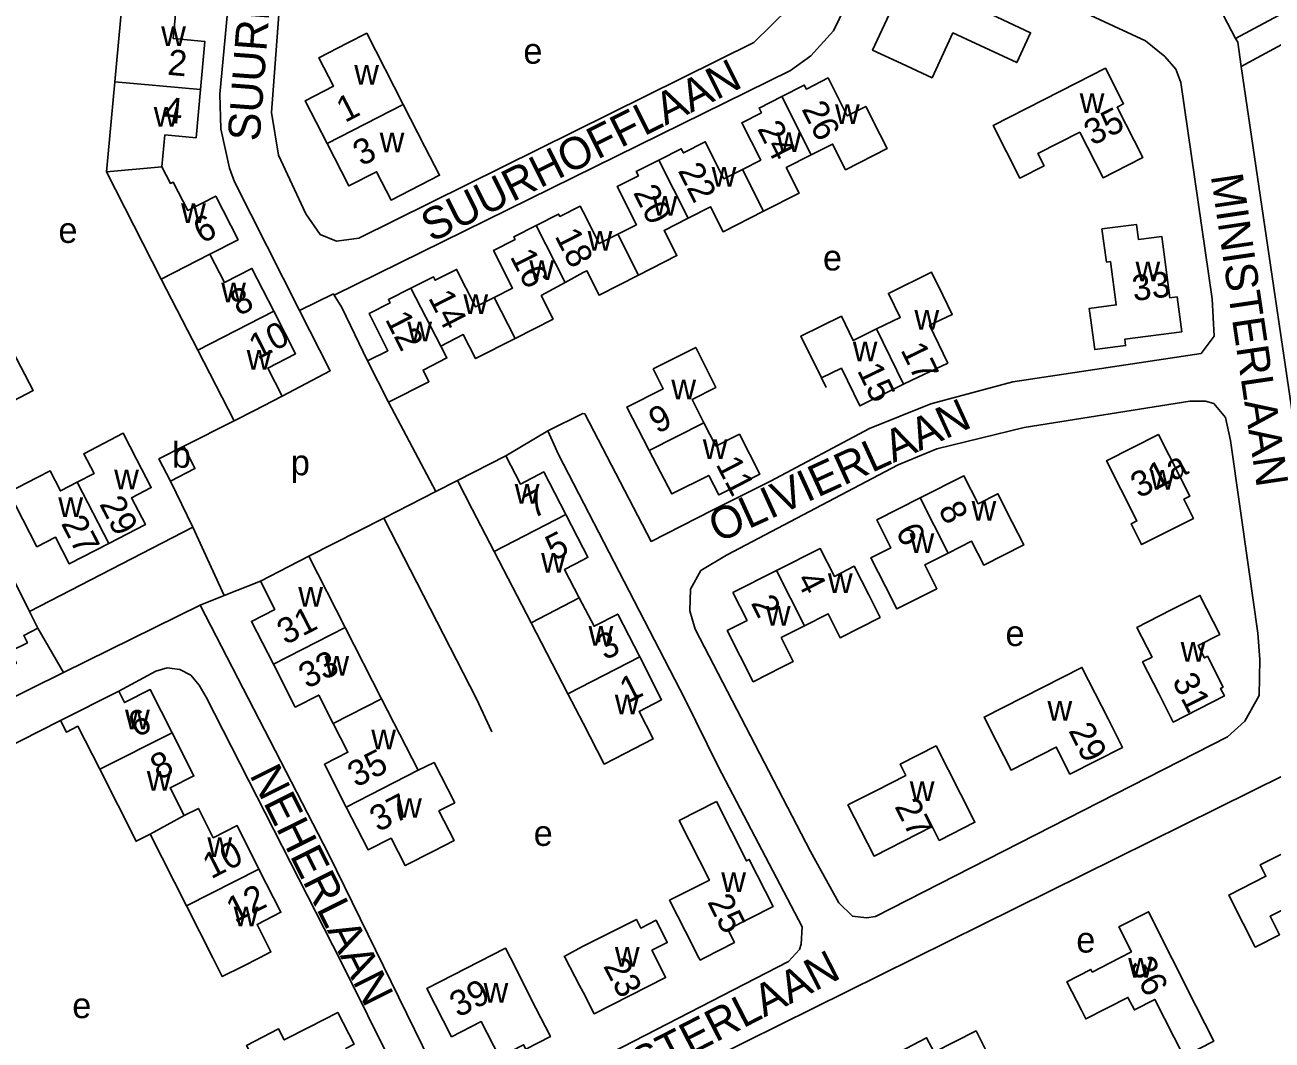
# Model space of a CAD drawing. Extents: x 162427 to 165104, y 384242 to 386287.
# Drawn here: x 163912.8 to 164107.7, y 384987.1 to 385145.8 of the extents above; entities that cross this region are included whole.
import ezdxf

# ---------------------------------------------------------------- set-up
doc = ezdxf.new("R2010")
doc.units = 0
for name, color, linetype in [('BLT_Basislijn', 7, 'Continuous'), ('BLT_Bebouwing', 7, 'Continuous'), ('BLT_Centroide', 7, 'Continuous'), ('BLT_Huisnummer', 7, 'Continuous'), ('BLT_Huisnummer_ tussenligend', 7, 'Continuous'), ('BLT_Onderverdeling_panden', 7, 'Continuous'), ('BLT_Straatnaam', 7, 'Continuous')]:
    doc.layers.add(name, color=color, linetype=linetype)

msp = doc.modelspace()

# ---------------------------------------------------------------- linework, layer by layer
at = {"layer": 'BLT_Basislijn'}
for p, q in [((164100.08, 385147.29), (164101.95, 385143.68)), ((163976.99, 385072.86), (163969.59, 385086.84)), ((163987.89, 385078.48), (163994.5, 385082.38)), ((163976.99, 385072.86), (163980.35, 385074.58)), ((163968.85, 385068.73), (163976.99, 385072.86)), ((163957.11, 385062.75), (163968.85, 385068.73)), ((163939, 385067.3), (163943.91, 385056.61)), ((163943.91, 385056.61), (163949.56, 385058.89)), ((163940.13, 385055.09), (163918.79, 385044.59)), ((163940.13, 385055.09), (163943.91, 385056.61)), ((163918.79, 385044.59), (163914.79, 385051.52)), ((163870.49, 385020.87), (163918.79, 385044.59)), ((163941.1, 385040.74), (163962.18, 384999.38)), ((163962.18, 384999.38), (163973.24, 384977.11))]:
    msp.add_line(p, q, dxfattribs=at)
for points in [[(163888.92, 385099.03), (163892.17, 385100.78), (163883.54, 385118.73), (163882.35, 385122.09), (163882.92, 385132.31), (163886.87, 385181.05), (163887.24, 385182.8), (163888.99, 385185.31), (163890.71, 385185.84), (163892.89, 385185.88), (163936.03, 385182.55), (163944.89, 385181.59), (163946.8, 385179.9), (163947.05, 385176.26), (163943.23, 385134.98), (163943.39, 385129.54), (163944.73, 385123.43), (163945.53, 385121.28), (163955.66, 385101.15)], [(164028.62, 385170.3), (164036.3, 385167.05), (164039, 385164.73), (164039.21, 385162.28), (164034.17, 385151.84), (164032.22, 385148.46), (164026.69, 385143.03), (163964.96, 385112.45), (163961.43, 385111.99), (163958.89, 385113.06), (163956.66, 385116.27), (163952.37, 385125.43), (163951.27, 385132.11), (163954.57, 385176.02), (163955.8, 385178.75), (163958.6, 385180.24), (164005.85, 385176.18), (164014.12, 385174.75), (164025.4, 385171.51), (164028.62, 385170.3)], [(164101.95, 385143.68), (164139.93, 385164.03), (164144.2, 385165.75), (164147.78, 385165.76), (164157.35, 385163.13)], [(163961.08, 385103.59), (164032.42, 385138.66), (164035.6, 385140.95), (164039.13, 385144.88), (164045.75, 385158.55), (164047.12, 385160.3), (164047.83, 385160.67), (164049.6, 385160.76), (164052.46, 385159.79), (164087.89, 385143.32)], [(164146.05, 385006.5), (164163.21, 385013.65), (164158.19, 385046.13), (164162.37, 385048.39), (164162.37, 385049.63), (164147.21, 385159.13), (164137.48, 385158.1), (164102.85, 385139.32)], [(164087.89, 385143.32), (164090.9, 385140.87), (164092.61, 385138.88), (164093.41, 385136.82), (164098.31, 385102.98), (164098.61, 385097.14), (164096.57, 385094.47)], [(164102.85, 385139.32), (164102.33, 385143.09), (164101.95, 385143.68)], [(163874.37, 384930.96), (163895.29, 384941.69), (163907.09, 384947.2), (163917.37, 384950.98), (163935.42, 384955.81), (163969.74, 384962.82), (163983.96, 384967.15), (163993.92, 384971.28), (164109.67, 385028.61), (164113.77, 385032.85), (164114.66, 385034.28), (164116.64, 385039.21), (164117.08, 385045.22), (164111.4, 385081.45), (164102.85, 385139.32)], [(163961.08, 385103.59), (163960.97, 385103.77), (163955.66, 385101.15)], [(163961.08, 385103.59), (163962.26, 385101.63), (163966.32, 385093.28)], [(163955.66, 385101.15), (163960.47, 385091.75), (163952.96, 385087.76)], [(164096.57, 385094.47), (164067.16, 385090.04), (164054.34, 385086.6), (164044.73, 385082.71), (164029.29, 385074.51)], [(164039.96, 385008.59), (164035.53, 385016.61), (164017.53, 385051.36), (164016.65, 385054.22), (164016.79, 385057.6), (164018.39, 385060.53), (164022.4, 385062.94), (164049.25, 385077.07), (164055.29, 385079.55), (164068.91, 385082.88), (164094.82, 385087.01), (164097.29, 385086.99), (164098.56, 385086.62)], [(164098.56, 385086.62), (164100.4, 385084.46), (164101.17, 385080.86), (164104.04, 385060.69)], [(164029.29, 385074.51), (164020.24, 385069.94), (164010.62, 385065.08), (164000.25, 385085.01), (163999.93, 385085.09), (163994.5, 385082.38)], [(163937.57, 385079.94), (163945.43, 385083.91)], [(164034.23, 385004.85), (164021.11, 385029.92), (164015.91, 385040.5), (163996.13, 385078.68), (163994.5, 385082.38)], [(163939, 385067.3), (163935.51, 385074.48)], [(163985.71, 385035.3), (163983.32, 385040.48), (163968.85, 385068.73)], [(163913.48, 385054.15), (163939, 385067.3)], [(164104.04, 385060.69), (164105.47, 385050.72), (164105.75, 385046.63), (164105.66, 385041.02), (164103.43, 385036.98), (164100.73, 385034.53), (164045.68, 385006.44), (164044.31, 385006.24), (164042.09, 385006.5), (164039.96, 385008.59)], [(163940.13, 385055.09), (163960.26, 385016.14), (163976.07, 384983.78), (163978.19, 384979.93), (163980.14, 384977.23), (163981.99, 384976.21)], [(163927.43, 385041.67), (163933.2, 385044.82), (163935, 385045.3), (163936.98, 385045.08), (163938.68, 385044.17), (163939.98, 385042.61), (163941.1, 385040.74)], [(163906.86, 384965.23), (163881.83, 385014.14), (163881.52, 385015.8), (163881.9, 385017.28), (163882.89, 385018.8), (163884.23, 385019.8), (163918.33, 385037.07)], [(163981.99, 384976.21), (163987.3, 384976.37), (164032.07, 384999.44), (164033.82, 385001.29), (164034.1, 385002.11), (164034.23, 385004.85)]]:
    msp.add_lwpolyline(points, dxfattribs=at)
at = {"layer": 'BLT_Bebouwing'}
for p, q in [((163926.79, 385136.92), (163925.49, 385122.82)), ((163925.49, 385122.82), (163934.07, 385106.07)), ((163934.07, 385106.07), (163939.75, 385094.99)), ((163997.2, 385105.56), (164000, 385107.1)), ((163939.75, 385094.99), (163945.43, 385083.91)), ((163969.59, 385086.84), (163966.32, 385093.28)), ((164037.24, 385090.63), (164037.96, 385089.14)), ((164050.09, 385089.64), (164051.36, 385090.27)), ((164047.36, 385088.3), (164050.09, 385089.64)), ((163987.89, 385078.48), (163980.35, 385074.58)), ((163962.8, 385051.62), (163957.11, 385062.75)), ((163986.11, 385063.48), (163991.87, 385052.36)), ((163910.8, 385059.49), (163913.48, 385054.15)), ((163913.48, 385054.15), (163914.79, 385051.52)), ((163968.5, 385040.47), (163962.8, 385051.62)), ((163991.87, 385052.36), (163997.61, 385041.27)), ((163918.33, 385037.07), (163927.43, 385041.67)), ((163974.21, 385029.31), (163968.5, 385040.47)), ((163932.34, 385019.34), (163938, 385008.15))]:
    msp.add_line(p, q, dxfattribs=at)
for points in [[(164067.83, 385140.05), (164069.93, 385144.59), (164060.26, 385149.08), (164060.46, 385149.51), (164049.66, 385154.53), (164046.99, 385148.77), (164048.19, 385148.21), (164045.24, 385141.86), (164049.78, 385139.76), (164054.54, 385137.55), (164057.79, 385144.55), (164067.76, 385139.92), (164067.83, 385140.05)], [(163940.18, 385135.69), (163940.87, 385143.21), (163935.93, 385143.66), (163936.38, 385148.52), (163931.4, 385148.98), (163927.93, 385149.3), (163926.79, 385136.92)], [(163971.87, 385133.39), (163966.17, 385144.5), (163963.13, 385142.94), (163958.68, 385140.66), (163960.96, 385136.21), (163956.56, 385133.96), (163959.98, 385127.29)], [(164083, 385122.81), (164087.46, 385125.08), (164083.45, 385132.94), (164084.48, 385133.47), (164081.64, 385139.04), (164077.18, 385136.76), (164064.06, 385130.07), (164068.25, 385121.86), (164072.03, 385123.79), (164071.06, 385125.69), (164077.62, 385129.04), (164081.26, 385121.92), (164083, 385122.81)], [(164031.03, 385134.61), (164034.57, 385136.4), (164034.89, 385135.78), (164038.28, 385137.51), (164041.28, 385131.59), (164044.17, 385133.06), (164046.43, 385128.6), (164047.51, 385126.47), (164041.01, 385123.17), (164038.98, 385127.17), (164035.65, 385125.49)], [(163934.16, 385123.6), (163934.62, 385128.62), (163939.49, 385128.17), (163940.18, 385135.69)], [(163959.98, 385127.29), (163963.39, 385120.63), (163967.71, 385122.85), (163969.98, 385118.42), (163977.55, 385122.3), (163975.27, 385126.75), (163971.87, 385133.39)], [(164024.89, 385123.21), (164027.76, 385124.67), (164024.79, 385130.52), (164027.86, 385132.08), (164027.49, 385132.81), (164031.03, 385134.61)], [(164011.82, 385124.66), (164015.34, 385126.44), (164015.66, 385125.81), (164019.08, 385127.54), (164022.01, 385121.75), (164024.89, 385123.21)], [(164028.19, 385116.69), (164033.77, 385119.52), (164031.75, 385123.51), (164035.65, 385125.49)], [(163941.67, 385109.96), (163946.07, 385112.21), (163942.57, 385119.05), (163938.2, 385116.81), (163935.92, 385121.25), (163935.48, 385121.02), (163934.16, 385123.6)], [(164005.42, 385113.1), (164008.33, 385114.58), (164005.31, 385120.54), (164008.63, 385122.22), (164008.3, 385122.87), (164011.82, 385124.66)], [(163992.66, 385114.47), (163996.16, 385116.25), (163996.36, 385115.87), (163999.53, 385117.49), (164000, 385116.57), (164002.52, 385111.63), (164005.42, 385113.1)], [(164016.42, 385115.58), (164019.92, 385117.35), (164021.88, 385113.49), (164028.19, 385116.69)], [(164008.67, 385106.71), (164014.65, 385109.75), (164012.66, 385113.68), (164016.42, 385115.58)], [(163986.09, 385103.19), (163988.98, 385104.66), (163985.99, 385110.55), (163989.37, 385112.28), (163989.16, 385112.69), (163992.66, 385114.47)], [(164081.51, 385113.98), (164086.47, 385114.63), (164086.78, 385112.27), (164090.43, 385112.75), (164091.69, 385103.17), (164092.84, 385103.32), (164093.56, 385097.84), (164084.64, 385096.67), (164084.77, 385095.68), (164079.96, 385095.05), (164079.31, 385100), (164079.11, 385101.49), (164083.32, 385102.05), (164082.42, 385108.82), (164081.78, 385108.74), (164081.09, 385113.93), (164081.51, 385113.98)], [(163951.64, 385101.08), (163948.23, 385107.75), (163943.93, 385105.55), (163941.67, 385109.96)], [(163973.08, 385104.65), (163976.59, 385106.44), (163976.87, 385105.9), (163980.21, 385107.6), (163983.2, 385101.72), (163986.09, 385103.19)], [(163997.2, 385105.56), (163993.44, 385103.5), (163995.31, 385099.82), (163989.35, 385096.79)], [(164000, 385107.1), (164000.58, 385107.38), (164002.5, 385103.59), (164008.67, 385106.71)], [(164045.87, 385098.29), (164049.55, 385100.09), (164047.71, 385103.85), (164054.46, 385107.14), (164056.2, 385103.58), (164057.68, 385100.55), (164054.15, 385098.87), (164056.98, 385092.96), (164051.36, 385090.27)], [(163966.32, 385093.28), (163969.49, 385094.89), (163966.55, 385100.68), (163969.83, 385102.35), (163969.57, 385102.87), (163973.08, 385104.65)], [(163952.96, 385087.76), (163950.7, 385092.17), (163955.06, 385094.41), (163951.64, 385101.08)], [(164037.24, 385090.63), (164034.04, 385097.18), (164040.36, 385100.26), (164042.19, 385096.5), (164045.87, 385098.29)], [(163896.68, 385090.86), (163899.61, 385085.21), (163903.77, 385087.37), (163905.42, 385084.19), (163909.86, 385086.49), (163914.02, 385088.65), (163910.79, 385094.89), (163907.72, 385093.3), (163906.38, 385095.89)], [(163989.35, 385096.79), (163983.18, 385093.65), (163981.27, 385097.4), (163977.77, 385095.62)], [(163977.77, 385095.62), (163978.72, 385093.75), (163974.98, 385091.85), (163975.9, 385090.04), (163969.59, 385086.84)], [(164010.32, 385079.3), (164006.81, 385086.07), (164012.52, 385088.95), (164010.96, 385092.04), (164014.08, 385093.61), (164017.6, 385095.39), (164020.75, 385089.14), (164017.04, 385087.27), (164018.88, 385083.62)], [(164047.36, 385088.3), (164043.23, 385086.26), (164040.37, 385092.15), (164037.24, 385090.63)], [(163945.43, 385083.91), (163948.51, 385085.49), (163952.96, 385087.76)], [(164018.88, 385083.62), (164020.72, 385079.97), (164024.43, 385081.84), (164027.6, 385075.57), (164021.21, 385072.34), (164019.63, 385075.39), (164013.84, 385072.51), (164010.32, 385079.3)], [(163925.87, 385064.76), (163931.59, 385067.71), (163929.42, 385071.91), (163932.5, 385073.5), (163930.21, 385077.94), (163928.13, 385081.98), (163921.95, 385078.79), (163923.55, 385075.68), (163920.92, 385074.32)], [(164090.93, 385066.42), (164087.28, 385064.58), (164085.64, 385067.82), (164086.56, 385068.29), (164084.06, 385073.23), (164081.8, 385077.69), (164089.92, 385081.8), (164094.81, 385072.14), (164093.88, 385071.67), (164095.39, 385068.68), (164090.93, 385066.42)], [(163937.57, 385079.94), (163933.7, 385077.98), (163935.51, 385074.48)], [(163935.51, 385074.48), (163939.33, 385076.46), (163937.57, 385079.94)], [(163997.3, 385069.28), (163993.84, 385075.95), (163990.19, 385074.05), (163987.89, 385078.48)], [(163920.92, 385074.32), (163918.29, 385072.97), (163916.68, 385076.09), (163914.67, 385075.05), (163910.22, 385072.76), (163914.62, 385064.24), (163917.54, 385065.74), (163919.69, 385061.57), (163925.87, 385064.76)], [(163980.35, 385074.58), (163982.65, 385070.14), (163986.11, 385063.48)], [(164057.05, 385063.24), (164060.72, 385065.1), (164062.6, 385061.38), (164068.86, 385064.54), (164067.08, 385068.07), (164064.82, 385072.54), (164061.72, 385070.97), (164059.52, 385075.31), (164052.7, 385071.87)], [(164052.7, 385071.87), (164045.88, 385068.43), (164048.07, 385064.07), (164044.99, 385062.52), (164047.24, 385058.05), (164049.03, 385054.52), (164055.29, 385057.68), (164053.4, 385061.4), (164057.05, 385063.24)], [(163999.4, 385056.26), (163997.1, 385060.71), (164000, 385062.21), (164000.75, 385062.6), (164000, 385064.05), (163997.3, 385069.28)], [(163957.11, 385062.75), (163954.01, 385061.17), (163949.56, 385058.89)], [(164034.59, 385051.91), (164038.27, 385053.77), (164040.16, 385050.03), (164046.42, 385053.21), (164044.63, 385056.74), (164042.37, 385061.2), (164039.26, 385059.62), (164037.05, 385063.97), (164030.23, 385060.53)], [(163949.56, 385058.89), (163951.83, 385054.45), (163948.16, 385052.57), (163951.58, 385045.88)], [(164030.23, 385060.53), (164023.42, 385057.09), (164025.63, 385052.72), (164022.53, 385051.15), (164026.58, 385043.15), (164031.04, 385045.41), (164032.84, 385046.33), (164030.95, 385050.06), (164034.59, 385051.91)], [(164008.84, 385047.03), (164005.41, 385053.72), (164001.71, 385051.82), (163999.4, 385056.26)], [(164091.93, 385054.38), (164096.39, 385056.65), (164099.49, 385050.54), (164096.12, 385048.82), (164097.11, 385046.88), (164097.58, 385047.12), (164100.03, 385042.31), (164099.62, 385042.1), (164100.22, 385040.92), (164092.23, 385036.85), (164089.96, 385041.31), (164087.45, 385046.24), (164088.92, 385046.99), (164086.56, 385051.65), (164091.93, 385054.38)], [(163903.39, 385044.28), (163906.07, 385045.62), (163906.98, 385043.8), (163911.43, 385046.03), (163910.48, 385047.92), (163913.13, 385049.25), (163912.56, 385050.4), (163914.79, 385051.52)], [(163951.58, 385045.88), (163955.01, 385039.19), (163958.67, 385041.07), (163960.95, 385036.61)], [(163997.61, 385041.27), (164000, 385036.66), (164003.29, 385030.28), (164006.49, 385031.93), (164010.94, 385034.21), (164008.73, 385038.52), (164012.27, 385040.33), (164008.84, 385047.03)], [(164082.04, 385037.35), (164077.95, 385045.39), (164062.67, 385037.62), (164064.62, 385033.79), (164066.88, 385029.34), (164073.95, 385032.93), (164076.09, 385028.71), (164084.31, 385032.89), (164082.04, 385037.35)], [(163935.76, 385035.18), (163932.35, 385041.91), (163928.34, 385039.88), (163927.43, 385041.67)], [(163918.33, 385037.07), (163919.24, 385035.28), (163921.04, 385036.19), (163923.3, 385031.73), (163924.45, 385029.46)], [(163960.95, 385036.61), (163963.23, 385032.14), (163959.55, 385030.26), (163962.98, 385023.57)], [(163935.76, 385035.18), (163939.16, 385028.44), (163935.43, 385026.55), (163937.62, 385022.22)], [(164058.96, 385025.63), (164061.23, 385021.18), (164055.65, 385018.34), (164054.55, 385020.51), (164045.46, 385015.89), (164041.39, 385023.91), (164045.85, 385026.17), (164050.43, 385028.51), (164049.54, 385030.26), (164055.16, 385033.12), (164058.96, 385025.63)], [(163962.98, 385023.57), (163966.4, 385016.87), (163969.98, 385018.7), (163972.17, 385014.41), (163976.62, 385016.69), (163979.83, 385018.33), (163977.46, 385022.96), (163979.94, 385024.23), (163976.71, 385030.55), (163974.21, 385029.31)], [(163924.45, 385029.46), (163930.12, 385018.22), (163932.34, 385019.34)], [(164020.82, 385024.42), (164025.51, 385015.15), (164025.96, 385015.38), (164029.69, 385008.02), (164022.61, 385004.45), (164023.65, 385002.4), (164018.98, 385000), (164018.29, 384999.64), (164018.1, 385000), (164016.02, 385004.1), (164013.51, 385009.01), (164019.74, 385012.16), (164015.02, 385021.48), (164020.82, 385024.42)], [(163937.62, 385022.22), (163939.86, 385023.35), (163942.18, 385018.77), (163945.91, 385020.66), (163949.33, 385013.88)], [(164120.29, 385017.9), (164118.02, 385022.36), (164110.02, 385018.29), (164110.69, 385016.98), (164105.83, 385014.51), (164106.72, 385012.76), (164100.91, 385009.8), (164103.17, 385005.35), (164105.04, 385001.68), (164108.84, 385003.61), (164107.36, 385006.51), (164114.45, 385010.11), (164114.87, 385009.29), (164122.65, 385013.25), (164120.29, 385017.9)], [(163938, 385008.15), (163942.12, 385000), (163943.6, 384997.07), (163946.75, 384998.66), (163949.4, 385000), (163951.21, 385000.92), (163949.03, 385005.23), (163952.76, 385007.11), (163949.33, 385013.88)], [(164095.76, 384992.48), (164088.37, 385007.19), (164083.71, 385004.82), (164085.68, 385000.94), (164083.86, 385000), (164079.58, 384997.77), (164079.36, 384998.19), (164075.6, 384996.27), (164077.87, 384991.81), (164078.56, 384990.45), (164085.15, 384993.82), (164086.15, 384991.87), (164089.34, 384993.5), (164093.88, 384984.6), (164098.56, 384986.99), (164095.76, 384992.48)], [(164000, 385001.81), (164008.33, 385006.01), (164009, 385004.66), (164011.4, 385005.86), (164013.14, 385002.39), (164010.74, 385001.19), (164011.34, 385000), (164012.89, 384996.91), (164001.7, 384991.25), (164000, 384994.61), (163999.45, 384995.66), (163997.17, 385000), (163997.05, 385000.23), (164000, 385001.81)], [(163988.62, 385000), (163992.61, 384992.13), (163994.89, 384987.68), (163991.04, 384985.71), (163990.68, 384986.42), (163986.9, 384984.49), (163984.06, 384990.03), (163979.44, 384987.66), (163975.57, 384995.22), (163987.85, 385001.51), (163988.62, 385000)], [(163967.14, 384977.65), (163962.93, 384985.83), (163964.21, 384986.48), (163961.65, 384991.46), (163957.2, 384989.18), (163953.28, 384987.17), (163952.4, 384988.88), (163947.36, 384986.29), (163951.4, 384978.41), (163953.69, 384973.96), (163961, 384977.71), (163962.3, 384975.17), (163967.14, 384977.65)], [(164063.69, 384984.13), (164061.42, 384988.58), (164054.85, 384985.23), (164053.68, 384987.51), (164043.03, 384981.93), (164045.3, 384977.48), (164046.79, 384974.57), (164057.18, 384979.87), (164057.71, 384978.83), (164064.6, 384982.34), (164063.69, 384984.13)]]:
    msp.add_lwpolyline(points, dxfattribs=at)
at = {"layer": 'BLT_Onderverdeling_panden'}
for p, q in [((163940.18, 385135.69), (163926.79, 385136.92)), ((163959.98, 385127.29), (163971.87, 385133.39)), ((164031.03, 385134.61), (164035.65, 385125.49)), ((163925.49, 385122.82), (163934.16, 385123.6)), ((164011.82, 385124.66), (164016.42, 385115.58)), ((164024.89, 385123.21), (164028.19, 385116.69)), ((163992.66, 385114.47), (163997.2, 385105.56)), ((164005.42, 385113.1), (164008.67, 385106.71)), ((163941.67, 385109.96), (163934.07, 385106.07)), ((163973.08, 385104.65), (163977.77, 385095.62)), ((163986.09, 385103.19), (163989.35, 385096.79)), ((163951.64, 385101.08), (163939.75, 385094.99)), ((164045.87, 385098.29), (164050.09, 385089.64)), ((164018.88, 385083.62), (164010.32, 385079.3)), ((163920.92, 385074.32), (163925.87, 385064.76)), ((164052.7, 385071.87), (164057.05, 385063.24)), ((163997.3, 385069.28), (163986.11, 385063.48)), ((164030.23, 385060.53), (164034.59, 385051.91)), ((163999.4, 385056.26), (163991.87, 385052.36)), ((163951.58, 385045.88), (163962.8, 385051.62)), ((164008.84, 385047.03), (163997.61, 385041.27)), ((163960.95, 385036.61), (163968.5, 385040.47)), ((163935.76, 385035.18), (163924.45, 385029.46)), ((163962.98, 385023.57), (163974.21, 385029.31)), ((163937.62, 385022.22), (163932.34, 385019.34)), ((163949.33, 385013.88), (163938, 385008.15))]:
    msp.add_line(p, q, dxfattribs=at)

# ---------------------------------------------------------------- texts
at = {"layer": 'BLT_Centroide'}
for s, p in [('w', (163934.05, 385142.5)), ('e', (163990.66, 385139.74)), ('w', (163964.22, 385136.48)), ('w', (164077.61, 385132.05)), ('w', (163932.89, 385129.88)), ('w', (164039.37, 385130.34)), ('w', (163968.2, 385125.91)), ('w', (164030.22, 385125.95)), ('w', (164020.08, 385120.53)), ('w', (163937.16, 385114.84)), ('w', (164010.86, 385116)), ('e', (163917.99, 385111.73)), ('w', (164000.7, 385110.53)), ('e', (164037.48, 385107.43)), ('w', (163991.59, 385105.94)), ('w', (164086.33, 385105.75)), ('w', (163943.43, 385102.47)), ('w', (163981.28, 385100.62)), ('w', (164051.78, 385098.16)), ('w', (163972.52, 385096.34)), ('w', (164042.14, 385093.25)), ('w', (163947.41, 385091.91)), ('w', (164013.78, 385087.27)), ('b', (163935.73, 385076.6)), ('w', (164018.7, 385077.97)), ('p', (163954.31, 385075.42)), ('w', (163926.7, 385073.22)), ('w', (164088.59, 385073.19)), ('w', (163989.31, 385070.97)), ('w', (163917.97, 385068.88)), ('w', (164060.71, 385068.34)), ('w', (164051.02, 385063.28)), ('w', (163993.42, 385060.22)), ('w', (164038.26, 385057)), ('w', (163955.48, 385054.89)), ('w', (164028.56, 385051.92)), ('w', (164000.84, 385048.78)), ('e', (164066.01, 385048.73)), ('w', (164093.39, 385046.28)), ('w', (163959.56, 385044.12)), ('w', (164004.94, 385038.08)), ('w', (164072.57, 385037.06)), ('w', (163928.4, 385035.69)), ('w', (163966.88, 385032.59)), ('w', (163931.8, 385026.12)), ('w', (164051.05, 385024.5)), ('w', (163970.93, 385021.88)), ('e', (163992.27, 385017.49)), ('w', (163941.27, 385015.75)), ('w', (164021.59, 385010.28)), ('w', (163945.38, 385004.92)), ('e', (164077.08, 385000.82)), ('w', (164004.96, 384998.62)), ('w', (164085.19, 384996.91)), ('w', (163984.44, 384993)), ('e', (163920.15, 384990.57))]:
    msp.add_text(s, height=4, dxfattribs=at).set_placement(p)
at = {"layer": 'BLT_Huisnummer'}
for s, rotation, p in [('2', 354.735, (163934.94, 385138.03)), ('1', 27.1366, (163962.77, 385130.47)), ('26', 296.8813, (164034.07, 385132.67)), ('35', 27.0423, (164079.61, 385126.86)), ('3', 27.1345, (163965.35, 385123.65)), ('20', 296.8835, (164007.75, 385119.61)), ('6', 27.1267, (163940.4, 385111.55)), ('16', 296.9683, (163988.5, 385109.61)), ('33', 7.4995, (164086.06, 385102.62)), ('12', 296.9693, (163968.97, 385099.83)), ('10', 27.1345, (163949.1, 385093.42)), ('17', 295.9998, (164049.55, 385095.03)), ('15', 295.9002, (164042.76, 385091.82)), ('9', 26.7615, (164011.57, 385081.84)), ('11', 297.3936, (164020.66, 385077.14)), ('31a', 26.8469, (164086.87, 385071.76)), ('7', 27.3865, (163992.17, 385068.57)), ('29', 297.2883, (163924.32, 385070.93)), ('8', 296.8234, (164055.44, 385070.11)), ('27', 297.2788, (163918.33, 385067.9)), ('6', 296.8851, (164048.76, 385066.68)), ('4', 296.8851, (164033.24, 385059.13)), ('2', 296.8851, (164026.15, 385055.46)), ('31', 27.0837, (163953.48, 385048.84)), ('1', 27.1479, (164007.04, 385039.76)), ('31', 296.9596, (164091.98, 385043.29)), ('6', 26.8177, (163930.22, 385034.34)), ('29', 296.9596, (164075.79, 385035.52)), ('37', 27.0877, (163967.96, 385019.6)), ('27', 296.9554, (164048.61, 385023.67)), ('12', 26.8154, (163945.54, 385005.43)), ('25', 297.0164, (164019.34, 385008.74)), ('36', 297.0263, (164085.35, 384998.97)), ('23', 297.7041, (164003.08, 384998.72)), ('39', 27.118, (163980.46, 384990.6))]:
    msp.add_text(s, height=4, rotation=rotation, dxfattribs=at).set_placement(p)
at = {"layer": 'BLT_Huisnummer_ tussenligend'}
for s, rotation, p in [('4', 354.735, (163934.26, 385130.6)), ('24', 296.8835, (164027.15, 385129.59)), ('22', 296.8835, (164014.74, 385123.03)), ('18', 296.9683, (163995.49, 385112.82)), ('8', 27.1267, (163946.17, 385100.24)), ('14', 296.9693, (163975.73, 385103.17)), ('5', 27.1479, (163995.45, 385061.97)), ('3', 27.1479, (164003.43, 385046.43)), ('33', 27.0837, (163956.85, 385041.98)), ('8', 26.8177, (163933.67, 385027.69)), ('35', 27.0837, (163964.5, 385026.56)), ('10', 26.8177, (163941.86, 385012.26))]:
    msp.add_text(s, height=4, rotation=rotation, dxfattribs=at).set_placement(p)
at = {"layer": 'BLT_Straatnaam'}
for s, rotation, p in [('SUURHOFFLAAN', 85.6985, (163949.42, 385127.52)), ('SUURHOFFLAAN', 26.5644, (163976.3, 385111.76)), ('MINISTERLAAN', 278.4124, (164098.09, 385122.24)), ('OLIVIERLAAN', 24.5404, (164021.1, 385064.81)), ('NEHERLAAN', 296.5521, (163947.79, 385028.6)), ('MINISTERLAAN', 27.1771, (163996.57, 384974.36))]:
    msp.add_text(s, height=5, rotation=rotation, dxfattribs=at).set_placement(p)

doc.saveas('drawing.dxf')
